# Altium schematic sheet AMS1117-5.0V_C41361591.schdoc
size 127 x 101 mm
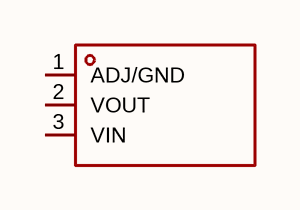
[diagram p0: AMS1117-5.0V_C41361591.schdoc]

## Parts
U?  ams1117-5.0v_c41361591  [SOT-89-3_L4.5-W2.5-P1.50-LS4.2-BR]  (value not drawn)

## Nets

Not connected (* = marked no-connect by the designer): U? 1(ADJ/GND) 2(VOUT) 3(VIN)

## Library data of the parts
U? = ams1117-5.0v_c41361591: 输出极性:正极;工作电压:15V;输出电压:5V;输出电流:1.2A;电源纹波抑制比(PSRR):-;输出类型:固定;; Manufacturer: JSMSEMI(杰盛微); AddInBom: yes; ModelId: 6db690b7897d4d18a30d90c1b89525ee; ModelName: SOT-89-3_L4.3-W2.5-H1.6-LS4.1-P1.50; ModelTransform: 161.417,169.291,0,180,0,0,-18.661,0,0; Output Configuration: 正极; Voltage - Supply: 15V; Output Voltage: 5V; Output Current: 1.2A; Voltage Dropout: 1.3V@(800mA); standby current: 2mA; Output Type: 固定; Number of Outputs: 1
